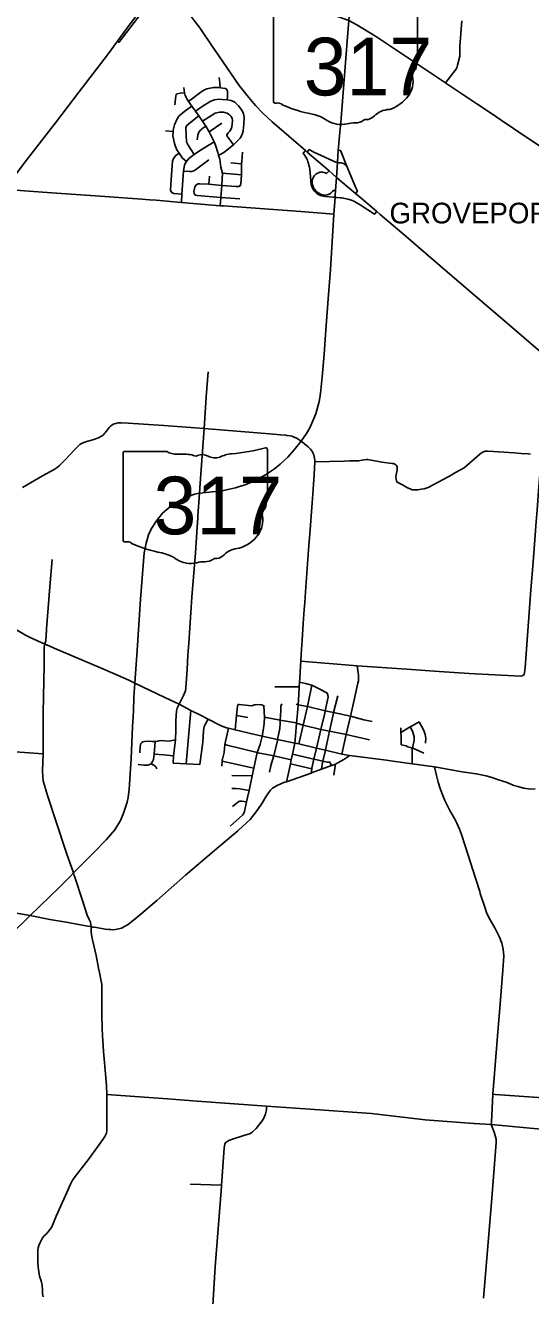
# Model space of a CAD drawing. Extents: x 1755200 to 1902939, y 644115 to 788070.
# Drawn here: x 1853497 to 1865704, y 661397 to 692073 of the extents above; entities that cross this region are included whole.
import ezdxf

# ---------------------------------------------------------------- set-up
doc = ezdxf.new("R2010")
doc.units = 0
for name, color, linetype in [('GM_X_City_Street', 7, 'Continuous'), ('GM_X_Corporation_Text', 7, 'Continuous'), ('GM_X_County_Road', 7, 'Continuous'), ('GM_X_Interchange_Ramps', 7, 'Continuous'), ('GM_X_Interstate_Route', 7, 'Continuous'), ('GM_X_State_Route', 7, 'Continuous'), ('GM_X_State_Shield', 7, 'Continuous'), ('GM_X_Township_Road', 7, 'Continuous'), ('GM_X_US_Route', 7, 'Continuous')]:
    doc.layers.add(name, color=color, linetype=linetype)

msp = doc.modelspace()

# ---------------------------------------------------------------- linework, layer by layer
at = {"layer": 'GM_X_City_Street'}
for points in [[(1860916, 692337), (1860948, 692324), (1861312, 692190), (1861508, 692091), (1861979, 691797), (1862752, 691283), (1863647, 690689), (1863658, 690682)], [(1858203, 687718), (1858220, 687916), (1858243, 688207), (1858260, 688504), (1858218, 688646), (1858192, 688840), (1858165, 688941), (1858149, 689003), (1858090, 689179), (1858055, 689260), (1857940, 689505), (1857859, 689641), (1857776, 689762), (1857687, 689888), (1857603, 690006), (1857519, 690120), (1857439, 690237), (1857411, 690278), (1857358, 690378), (1857340, 690447), (1857321, 690573)], [(1857439, 690237), (1857737, 690458), (1857805, 690506), (1857883, 690538), (1857959, 690561), (1858045, 690573), (1858206, 690570), (1858212, 690569), (1858334, 690548), (1858360, 690528), (1858380, 690484), (1858382, 690426), (1858379, 690345), (1858375, 690275)], [(1858206, 690570), (1858197, 690688), (1858181, 690816)], [(1857110, 690157), (1857129, 690373), (1857141, 690407), (1857167, 690422), (1857240, 690436), (1857340, 690447)], [(1857603, 690006), (1857796, 690131), (1857974, 690246), (1858062, 690272), (1858168, 690289), (1858251, 690281), (1858375, 690275), (1858471, 690261), (1858558, 690218), (1858600, 690182), (1858644, 690134), (1858701, 690060), (1858733, 690010)], [(1857388, 688788), (1857294, 688867), (1857212, 688986), (1857158, 689067), (1857124, 689149), (1857099, 689219), (1857057, 689408), (1857066, 689509), (1857068, 689541), (1857098, 689671), (1857158, 689802), (1857207, 689880), (1857269, 689941), (1857383, 690023), (1857519, 690120)], [(1857776, 689762), (1858083, 689955), (1858194, 689982), (1858280, 689980), (1858376, 689952), (1858430, 689912), (1858461, 689878)], [(1858165, 688941), (1858219, 688961), (1858289, 689001), (1858523, 689193), (1858577, 689237), (1858689, 689353), (1858733, 689442), (1858759, 689530), (1858778, 689685), (1858780, 689859), (1858765, 689937), (1858747, 689978), (1858733, 690010)], [(1857577, 688958), (1857428, 689185), (1857390, 689264), (1857371, 689600), (1857391, 689644), (1857451, 689708), (1857687, 689888)], [(1857651, 689308), (1857660, 689420), (1857688, 689493), (1857724, 689541), (1857782, 689589), (1857859, 689641)], [(1857940, 689505), (1858243, 689715)], [(1858461, 689878), (1858489, 689832), (1858503, 689772), (1858495, 689700), (1858482, 689622), (1858468, 689577), (1858436, 689523), (1858400, 689475), (1858362, 689433), (1858364, 689417), (1858380, 689383), (1858419, 689335), (1858523, 689193)], [(1856878, 689524), (1857066, 689509)], [(1857267, 687797), (1857279, 687994), (1857320, 688555), (1857333, 688661), (1857343, 688701), (1857358, 688737), (1857388, 688788), (1857411, 688820), (1857447, 688863), (1857577, 688958), (1857704, 689045), (1858055, 689260)], [(1858723, 688784), (1858723, 688787), (1858743, 689011)], [(1857279, 687994), (1857080, 688013), (1857033, 688035), (1856999, 688083), (1857010, 688238), (1857048, 688791), (1857074, 688856), (1857135, 688935), (1857212, 688986)], [(1857320, 688555), (1857473, 688545), (1857517, 688544), (1857553, 688555), (1857604, 688589), (1857927, 688829)], [(1858461, 688755), (1858718, 688732)], [(1858653, 688181), (1858685, 688198), (1858706, 688245), (1858721, 688463), (1858718, 688732), (1858723, 688784)], [(1857931, 688236), (1857948, 688434)], [(1858260, 688504), (1858721, 688463)], [(1853256, 688094), (1854025, 688040), (1855415, 687939), (1856313, 687875), (1856498, 687863), (1856659, 687849)], [(1857575, 688092), (1857568, 688060), (1857572, 688013), (1857600, 687977), (1857651, 687962), (1858220, 687916), (1858225, 687915)], [(1857575, 688092), (1857592, 688175), (1857626, 688224), (1857674, 688251), (1857713, 688251), (1857931, 688236), (1858243, 688207), (1858590, 688183), (1858653, 688181)], [(1856659, 687849), (1857267, 687797), (1858203, 687718), (1858280, 687713)], [(1858225, 687915), (1858677, 687884)], [(1858280, 687713), (1860155, 687580), (1860950, 687512)], [(1857862, 683100), (1857912, 683710)], [(1857819, 682336), (1857861, 683093), (1857862, 683100)], [(1853426, 680912), (1853522, 680967), (1853910, 681193), (1854189, 681352), (1854261, 681400), (1854318, 681445), (1854378, 681497), (1854453, 681572), (1854570, 681699), (1854684, 681827), (1854744, 681888), (1854816, 681949), (1854871, 681982), (1854933, 682010), (1855003, 682031), (1855128, 682068), (1855265, 682112), (1855307, 682133), (1855338, 682154), (1855372, 682181), (1855399, 682207), (1855422, 682234), (1855522, 682365), (1855552, 682391), (1855579, 682412), (1855608, 682431), (1855645, 682450), (1855680, 682462), (1855708, 682470), (1855738, 682474), (1855770, 682476), (1855812, 682476), (1855976, 682468), (1856838, 682407), (1857819, 682336), (1859494, 682198), (1859660, 682184), (1859789, 682175), (1859814, 682172)], [(1857662, 680176), (1857665, 680229), (1857704, 680773), (1857718, 681019), (1857819, 682336)], [(1859814, 682172), (1859893, 682164), (1859935, 682152), (1859974, 682139), (1860060, 682093), (1860156, 682029), (1860241, 681965), (1860329, 681899), (1860364, 681866), (1860388, 681838), (1860410, 681809), (1860430, 681778), (1860444, 681747), (1860464, 681703), (1860478, 681662), (1860486, 681621), (1860490, 681577), (1860492, 681535)], [(1863741, 681190), (1863892, 681274), (1864098, 681392), (1864474, 681719), (1864509, 681742), (1864533, 681756), (1864567, 681774), (1864606, 681792), (1864653, 681792)], [(1860247, 678135), (1860266, 678393), (1860341, 679406), (1860379, 679897), (1860436, 680648), (1860456, 680984), (1860475, 681227), (1860492, 681535)], [(1860492, 681535), (1861199, 681551), (1861335, 681555), (1861455, 681558), (1861492, 681557)], [(1861492, 681557), (1861502, 681557), (1861556, 681559), (1861629, 681570), (1861687, 681581), (1861735, 681586), (1861771, 681587), (1861800, 681585), (1861989, 681549), (1862111, 681528), (1862357, 681496), (1862384, 681490), (1862404, 681484), (1862427, 681476), (1862447, 681463), (1862461, 681447), (1862473, 681431), (1862476, 681417), (1862480, 681396), (1862480, 681371), (1862477, 681340), (1862456, 681216), (1862451, 681165), (1862455, 681118), (1862467, 681076), (1862477, 681042), (1862607, 680976), (1862731, 680909), (1862790, 680878), (1862844, 680860), (1862898, 680854), (1862977, 680858), (1863058, 680870), (1863132, 680885), (1863225, 680913), (1863231, 680916)], [(1852124, 678291), (1852293, 678171), (1852973, 677678), (1853115, 677579), (1853151, 677554), (1853239, 677497), (1853496, 677349), (1853612, 677287), (1853964, 677130), (1854004, 677115)], [(1853964, 677130), (1853984, 677186), (1853988, 677214), (1854008, 677475)], [(1853947, 676655), (1853951, 677068), (1853964, 677130)], [(1854004, 677115), (1854012, 677112), (1854194, 677034), (1854360, 676964), (1854629, 676848), (1855315, 676556), (1855608, 676432), (1855996, 676257), (1856143, 676188)], [(1857211, 675679), (1857307, 675873), (1857343, 675944), (1857362, 676003), (1857372, 676074), (1857405, 676517), (1857425, 676868), (1857431, 676963)], [(1856143, 676188), (1856869, 675838), (1857211, 675679), (1857493, 675528), (1857729, 675414), (1857909, 675320), (1858229, 675159), (1858353, 675112), (1858401, 675102), (1858567, 675061), (1858669, 675037)], [(1860005, 674735), (1860027, 674918), (1860049, 675225), (1860068, 675462), (1860084, 675668), (1860100, 675913), (1860114, 676102), (1860121, 676212), (1860127, 676304)], [(1860101, 674719), (1860206, 675175), (1860309, 675622), (1860415, 676136)], [(1860121, 676212), (1860267, 676183), (1860415, 676136), (1860610, 676040), (1860784, 675958), (1860801, 675911)], [(1859525, 676101), (1860114, 676102)], [(1860398, 674016), (1860415, 674121), (1860417, 674131), (1860468, 674353), (1860529, 674616), (1860637, 675067), (1860732, 675465), (1860743, 675520), (1860794, 675775), (1860809, 675847), (1860803, 675889), (1860801, 675911)], [(1860751, 674580), (1860847, 675025), (1860942, 675464), (1860945, 675477), (1861044, 675884)], [(1861141, 674476), (1861199, 674729), (1861246, 674946), (1861348, 675389), (1861464, 675893), (1861465, 675896)], [(1857069, 674256), (1857077, 674436), (1857126, 674822), (1857130, 675067), (1857131, 675278), (1857149, 675519), (1857161, 675580), (1857211, 675679)], [(1857380, 674241), (1857493, 675528)], [(1858567, 675061), (1858600, 675406), (1858619, 675635), (1858626, 675670)], [(1858626, 675670), (1858664, 675673), (1858886, 675651), (1858968, 675641), (1859031, 675665), (1859036, 675667), (1859045, 675668)], [(1859045, 675668), (1859101, 675674), (1859207, 675666), (1859237, 675652), (1859253, 675646)], [(1859173, 674715), (1859217, 674909), (1859242, 675045), (1859263, 675216), (1859277, 675363), (1859261, 675638), (1859263, 675628), (1859253, 675646)], [(1859585, 674801), (1859590, 674824), (1859641, 675093), (1859652, 675225), (1859654, 675295), (1859670, 675517), (1859672, 675634), (1859690, 675691)], [(1860042, 675679), (1860084, 675668), (1860309, 675622), (1860743, 675520), (1860945, 675477), (1861348, 675389), (1861674, 675303), (1861674, 675303)], [(1857714, 674224), (1857782, 674765), (1857798, 675037), (1857805, 675095), (1857817, 675140), (1857840, 675187), (1857909, 675320)], [(1858600, 675406), (1858871, 675360)], [(1859277, 675363), (1859654, 675295), (1860040, 675227)], [(1860040, 675227), (1860049, 675225), (1860206, 675175), (1860637, 675067), (1860847, 675025), (1861246, 674946), (1861813, 674817)], [(1861674, 675303), (1861872, 675258)], [(1862572, 674994), (1862793, 675132), (1862839, 675160), (1863013, 675254)], [(1863168, 674737), (1863170, 674857), (1863155, 674952), (1863122, 675042), (1863013, 675254)], [(1858257, 674353), (1858298, 674513), (1858319, 674709), (1858401, 675102)], [(1858669, 675037), (1858932, 674974), (1859217, 674909), (1859590, 674824), (1860005, 674735), (1860101, 674719), (1860529, 674616), (1860748, 674568), (1861141, 674476), (1861281, 674450)], [(1862577, 674702), (1862577, 674909), (1862572, 674994), (1862566, 675109)], [(1862840, 674240), (1862843, 674606), (1862847, 674619), (1862855, 674642), (1862869, 674698), (1862894, 674802), (1862893, 674888), (1862857, 675003), (1862824, 675074), (1862793, 675132)], [(1856259, 674506), (1856270, 674658), (1856276, 674702), (1856290, 674728), (1856310, 674754), (1856332, 674768), (1856376, 674782), (1856475, 674787), (1856557, 674781), (1856629, 674779)], [(1856539, 674242), (1856571, 674298), (1856589, 674342), (1856606, 674472), (1856629, 674779)], [(1856629, 674779), (1856693, 674791), (1856723, 674797), (1856765, 674800), (1856974, 674791), (1857003, 674797)], [(1857003, 674797), (1857126, 674822)], [(1858319, 674709), (1858368, 674687), (1858734, 674599)], [(1858447, 672732), (1858741, 673000), (1858767, 673034), (1858789, 673090), (1858841, 673322), (1858864, 673426), (1858902, 673599), (1858977, 673948), (1859018, 674134), (1859099, 674510), (1859170, 674704), (1859173, 674715)], [(1858734, 674599), (1859099, 674510), (1859124, 674505), (1859500, 674433), (1859919, 674339)], [(1859428, 674203), (1859500, 674433), (1859585, 674801)], [(1859806, 673807), (1859808, 673808), (1859845, 673982), (1859899, 674242), (1859919, 674339), (1859950, 674475), (1860005, 674735)], [(1860685, 674301), (1860687, 674307), (1860748, 674568), (1860748, 674568), (1860751, 674580)], [(1862577, 674702), (1862696, 674671), (1862741, 674653), (1862847, 674619), (1862855, 674616), (1862986, 674563), (1863126, 674500)], [(1854233, 672859), (1854030, 673476), (1853929, 673830), (1853917, 673924), (1853914, 674072), (1853927, 674485)], [(1856606, 674472), (1856841, 674454), (1856841, 674454)], [(1856841, 674454), (1857077, 674436)], [(1858246, 674186), (1858252, 674302), (1858254, 674341), (1858257, 674353)], [(1858252, 674302), (1859018, 674134)], [(1859950, 674475), (1860468, 674353), (1860477, 674351), (1860687, 674307), (1860790, 674281), (1860813, 674279), (1860843, 674286), (1860896, 674197)], [(1860410, 674021), (1860655, 674113), (1860896, 674197), (1860971, 674226), (1861189, 674344), (1861264, 674392), (1861324, 674441)], [(1860655, 674113), (1860678, 674271), (1860685, 674301)], [(1861281, 674450), (1861324, 674441), (1862222, 674325), (1862373, 674304)], [(1856220, 674223), (1856360, 674205), (1856452, 674206), (1856495, 674220), (1856539, 674242)], [(1856672, 674115), (1856653, 674159), (1856629, 674182), (1856599, 674208), (1856539, 674242)], [(1857069, 674256), (1857380, 674241), (1857714, 674224)], [(1859393, 674038), (1859426, 674195), (1859428, 674203)], [(1859808, 673808), (1860398, 674016), (1860410, 674021)], [(1859899, 674242), (1860415, 674121)], [(1860953, 673963), (1860982, 674183), (1860979, 674205), (1860971, 674226)], [(1858488, 673957), (1858977, 673948)], [(1859433, 673618), (1859447, 673630), (1859471, 673651), (1859562, 673712), (1859697, 673771), (1859765, 673793), (1859806, 673807)], [(1858481, 673646), (1858589, 673642), (1858679, 673633), (1858902, 673599)], [(1858497, 673209), (1858656, 673329), (1858680, 673335), (1858726, 673339), (1858841, 673322)], [(1854688, 671502), (1854675, 671541), (1854661, 671604), (1854486, 672082), (1854233, 672859)], [(1855134, 670298), (1855213, 670285), (1855425, 670250), (1855514, 670239), (1855561, 670236), (1855627, 670231), (1855715, 670247), (1855815, 670274), (1855892, 670309), (1855978, 670357), (1856284, 670609), (1856670, 670935), (1857365, 671549), (1858064, 672147), (1858630, 672623), (1858644, 672636)]]:
    msp.add_lwpolyline(points, dxfattribs=at)
at = {"layer": 'GM_X_County_Road'}
for points in [[(1863647, 690689), (1863896, 691006), (1863919, 691045), (1863941, 691117), (1863997, 691334), (1863994, 691569), (1864043, 692185)], [(1863658, 690682), (1864403, 690179), (1864782, 689927), (1864994, 689782), (1865287, 689585), (1865588, 689386), (1866376, 688859), (1866561, 688728), (1866664, 688651), (1866709, 688615)], [(1861513, 676603), (1862717, 676522), (1863496, 676469), (1864217, 676423), (1865458, 676355), (1865501, 676361), (1865531, 676379), (1865551, 676407), (1865559, 676440), (1865570, 676568), (1865711, 678443), (1865747, 678914), (1865778, 679328), (1865812, 679763), (1865837, 680091), (1865860, 680367), (1865898, 680836), (1865941, 681419), (1865951, 681544)], [(1857431, 676963), (1857442, 677153), (1857522, 678265), (1857604, 679332), (1857649, 679956), (1857662, 680176)], [(1860145, 676618), (1860153, 676717), (1860162, 676886), (1860184, 677224), (1860212, 677628), (1860234, 677965), (1860247, 678135)], [(1860127, 676304), (1860144, 676609), (1860145, 676618)], [(1861465, 675896), (1861529, 676184), (1861543, 676244), (1861549, 676293), (1861547, 676345), (1861543, 676392), (1861537, 676434), (1861513, 676603)], [(1862373, 674304), (1862840, 674240), (1863384, 674164), (1864053, 674044), (1864390, 674002), (1864630, 673951), (1864765, 673913), (1864929, 673857), (1865112, 673799), (1865280, 673728), (1865294, 673721), (1865297, 673720)], [(1864489, 671105), (1864473, 671154), (1864377, 671452), (1864120, 672259), (1864031, 672532), (1863985, 672663), (1863920, 672805), (1863863, 672918), (1863756, 673115), (1863634, 673354), (1863566, 673518), (1863515, 673643), (1863470, 673796), (1863426, 673955), (1863384, 674164)], [(1865297, 673720), (1865397, 673692), (1865536, 673653), (1865708, 673630), (1865811, 673635)], [(1858644, 672636), (1858928, 672897), (1859009, 672997), (1859110, 673134), (1859218, 673292), (1859309, 673446), (1859370, 673541), (1859420, 673607), (1859433, 673618)], [(1855082, 670307), (1855077, 670356), (1855067, 670412), (1855039, 670479), (1854992, 670586), (1854875, 670941), (1854688, 671502)], [(1864970, 668444), (1865034, 669256), (1865054, 669593), (1865039, 669765), (1865007, 669911), (1864949, 670055), (1864841, 670275), (1864704, 670513), (1864640, 670647), (1864594, 670775), (1864489, 671105)], [(1852096, 670831), (1853612, 670573)], [(1853612, 670573), (1854085, 670484), (1854528, 670409), (1854778, 670361)], [(1854778, 670361), (1854785, 670360), (1854999, 670321), (1855082, 670307)], [(1855343, 668206), (1855343, 668329), (1855342, 668614), (1855345, 668809), (1855341, 668910), (1855330, 668988), (1855286, 669200), (1855262, 669308), (1855207, 669612), (1855120, 669991), (1855095, 670107), (1855089, 670185), (1855082, 670307)], [(1855082, 670307), (1855134, 670298)], [(1864756, 665581), (1864756, 665582), (1864793, 666258), (1864900, 667663), (1864970, 668440), (1864970, 668444)], [(1855462, 666252), (1855453, 666460), (1855444, 666664), (1855384, 667293), (1855359, 667683), (1855351, 667833), (1855343, 668206)], [(1853907, 661550), (1853904, 661622), (1853899, 661649), (1853876, 661750), (1853840, 661863), (1853806, 662080), (1853797, 662207), (1853798, 662372), (1853800, 662491), (1853809, 662551), (1853824, 662606), (1853844, 662666), (1853874, 662727), (1853911, 662789), (1853958, 662845), (1853993, 662875), (1854045, 662935), (1854117, 663031), (1854141, 663077), (1854242, 663315), (1854353, 663562), (1854498, 663888), (1854588, 664085), (1854636, 664182), (1854702, 664271), (1855010, 664676), (1855248, 664999), (1855370, 665164), (1855418, 665236), (1855436, 665272), (1855455, 665316), (1855465, 665381), (1855465, 665667), (1855462, 666252)], [(1855462, 666252), (1856483, 666179), (1856930, 666146), (1857651, 666095), (1859326, 665971), (1860259, 665910), (1861859, 665794), (1863158, 665640), (1864334, 665557)], [(1864334, 665557), (1864338, 665557), (1864754, 665527)], [(1864569, 661334), (1864755, 663649), (1864875, 665092), (1864872, 665174), (1864827, 665345), (1864754, 665527), (1864756, 665581)], [(1864754, 665527), (1865692, 665442), (1866128, 665403), (1867408, 665311), (1867785, 665280), (1867804, 665280)], [(1853925, 661369), (1853910, 661437), (1853907, 661550)]]:
    msp.add_lwpolyline(points, dxfattribs=at)
at = {"layer": 'GM_X_Interchange_Ramps'}
for points in [[(1855721, 691691), (1855756, 691664), (1856207, 692249), (1856560, 692706), (1856777, 692989), (1857026, 693309), (1857514, 693941), (1857648, 694112), (1857735, 694222), (1858124, 694717), (1858076, 694754)], [(1860265, 689050), (1860207, 688985), (1860247, 688929), (1860271, 688891), (1860294, 688849), (1860310, 688815), (1860324, 688779), (1860338, 688738), (1860349, 688699), (1860360, 688646), (1860366, 688593), (1860404, 688229), (1860417, 688181), (1860432, 688145), (1860450, 688113), (1860475, 688077), (1860507, 688042), (1860533, 688020), (1860565, 687998), (1860598, 687980), (1860627, 687968), (1860665, 687957), (1860700, 687951), (1860747, 687943), (1860938, 687925), (1860978, 687922)], [(1861038, 688759), (1861010, 688760), (1860467, 689011), (1860355, 689074), (1860305, 689015)], [(1861471, 688017), (1861520, 688071), (1861478, 688150), (1861257, 688688), (1861132, 688992), (1861109, 689054), (1861058, 689057)], [(1861257, 688688), (1861245, 688683), (1861226, 688703), (1861204, 688721), (1861179, 688735), (1861150, 688747), (1861124, 688753), (1861105, 688755), (1861086, 688756), (1861038, 688759)], [(1860991, 688085), (1860937, 688089), (1860918, 688063), (1860893, 688037), (1860866, 688016), (1860838, 688000), (1860812, 687989), (1860786, 687981), (1860750, 687975), (1860715, 687974), (1860681, 687978), (1860644, 687988), (1860585, 688020), (1860545, 688048), (1860511, 688080), (1860480, 688120), (1860461, 688153), (1860448, 688184), (1860435, 688227), (1860428, 688271), (1860428, 688317), (1860437, 688366), (1860449, 688396), (1860463, 688423), (1860481, 688447), (1860511, 688477), (1860541, 688498), (1860577, 688515), (1860611, 688525), (1860645, 688529), (1860684, 688528), (1860715, 688522), (1860741, 688514), (1860776, 688498), (1860836, 688560)], [(1860978, 687922), (1861013, 687919), (1861112, 687912), (1861146, 687909), (1861184, 687903), (1861291, 687879), (1861374, 687852), (1861450, 687818), (1861516, 687784), (1861583, 687744), (1861930, 687513), (1861985, 687576)]]:
    msp.add_lwpolyline(points, dxfattribs=at)
at = {"layer": 'GM_X_Interstate_Route'}
for points in [[(1856737, 693020), (1856457, 692670), (1856025, 692109), (1855721, 691691)], [(1855721, 691691), (1855482, 691365), (1854785, 690465), (1854227, 689720), (1853491, 688775), (1852994, 688113)]]:
    msp.add_lwpolyline(points, dxfattribs=at)
at = {"layer": 'GM_X_State_Route'}
for points in [[(1861082, 689327), (1861118, 689728), (1861270, 691692), (1861312, 692190), (1861342, 692610)], [(1861072, 689219), (1861082, 689327)], [(1861015, 688403), (1861038, 688759), (1861058, 689057), (1861072, 689219)], [(1860982, 687976), (1860991, 688085), (1861015, 688403)], [(1860950, 687512), (1860978, 687922), (1860982, 687976)], [(1856430, 679624), (1856472, 679768), (1856544, 679921), (1856661, 680105), (1856809, 680290), (1857017, 680470), (1857125, 680541), (1857279, 680626), (1857475, 680711), (1857585, 680749), (1857704, 680773), (1858242, 680836), (1858431, 680872), (1858575, 680904), (1858844, 680992), (1859077, 681097), (1859302, 681221), (1859512, 681366), (1859654, 681474), (1859840, 681648), (1859988, 681821), (1860156, 682029), (1860291, 682215), (1860366, 682357), (1860443, 682525), (1860511, 682693), (1860595, 682989), (1860623, 683127), (1860637, 683268), (1860670, 683583), (1860712, 684123), (1860745, 684612), (1860816, 685471), (1860868, 686179), (1860950, 687512)], [(1856143, 676188), (1856195, 676985), (1856281, 678215), (1856367, 679337), (1856415, 679572), (1856430, 679624)], [(1856102, 675399), (1856109, 675507), (1856120, 675852), (1856143, 676188)], [(1854772, 671716), (1855159, 672106), (1855452, 672408), (1855656, 672644), (1855793, 672869), (1855865, 673048), (1855955, 673310), (1855982, 673423), (1856008, 673625), (1856056, 674364), (1856086, 675140), (1856101, 675376), (1856102, 675399)], [(1848819, 666696), (1849099, 666688), (1849232, 666701), (1849354, 666722), (1849455, 666750), (1849554, 666780), (1849673, 666832), (1849786, 666895), (1850303, 667340), (1851168, 668195), (1852000, 669022), (1852811, 669805), (1853162, 670133), (1853612, 670573), (1854310, 671256), (1854583, 671527)], [(1854583, 671527), (1854661, 671604), (1854772, 671716)]]:
    msp.add_lwpolyline(points, dxfattribs=at)
at = {"layer": 'GM_X_State_Shield'}
for p, q in [((1862974, 691331), (1862974, 692436)), ((1859493, 692347), (1859493, 690234)), ((1862973, 691331), (1862974, 691331)), ((1855863, 681748), (1855863, 679634)), ((1856916, 681784), (1855897, 681784)), ((1859343, 680731), (1859343, 681836)), ((1859343, 680731), (1859343, 680731))]:
    msp.add_line(p, q, dxfattribs=at)
for centre, major_axis, start_param, end_param in [((1862965, 691250), (60, 0), 1.883978, 3.671073), ((1862583, 691110), (360, 0), 5.934695, 6.695948), ((1862932, 691326), (41.5, 0), 5.05454, 6.418171), ((1861941, 690727), (923, 0), 5.101752, 6.440018), ((1863113, 690868), (262, 0), 2.387724, 3.262537), ((1859534, 690230), (40.7, 0), 3.00124, 4.508301), ((1859540, 690446), (310, 0), 4.665946, 4.897461), ((1859603, 690112), (112, 0), 0.519207, 1.627899), ((1861017, 692011), (2665, 0), 4.195997, 4.488961), ((1860222, 689285), (834, 0), 0.823519, 1.323587), ((1862330, 689641), (506, 0), 1.647645, 2.488434), ((1861124, 690102), (529, 0), 4.026481, 4.996735), ((1861430, 689371), (435, 0), 1.495662, 1.94098), ((1861468, 689943), (282, 0), 4.691044, 5.507374), ((1861723, 689739), (79.4, 0), 1.147584, 2.315152), ((1861689, 690029), (298, 0), 4.937069, 5.64225), ((1855902, 681752), (40.3, 0), 1.712693, 3.28349), ((1857159, 682029), (391, 0), 4.042523, 4.731795), ((1857289, 680597), (1404, 0), 1.404758, 1.657858), ((1857607, 681763), (113, 0), 3.836095, 5.185415), ((1857773, 681519), (235, 0), 0.950623, 2.079405), ((1858076, 681854), (282, 0), 4.081561, 5.145723), ((1858574, 681138), (743, 0), 1.699011, 2.107814), ((1858103, 684665), (3691, 0), 4.814394, 5.042369), ((1859304, 681841), (38.7, 0), 6.141152, 7.989035), ((1859302, 680727), (41.5, 0), 5.05454, 6.418171), ((1859482, 680268), (262, 0), 2.387724, 3.262537), ((1859334, 680650), (60, 0), 1.883978, 3.671073), ((1858953, 680510), (360, 0), 5.934695, 6.695948), ((1858310, 680128), (923, 0), 5.101752, 6.440018), ((1855903, 679630), (40.7, 0), 3.00124, 4.508301), ((1855909, 679846), (310, 0), 4.665946, 4.897461), ((1855973, 679512), (112, 0), 0.519207, 1.627899), ((1857386, 681411), (2665, 0), 4.195997, 4.488961), ((1856591, 678685), (834, 0), 0.823519, 1.323587), ((1857837, 679344), (282, 0), 4.691044, 5.507374), ((1858093, 679139), (79.4, 0), 1.147584, 2.315152), ((1858059, 679429), (298, 0), 4.937069, 5.64225), ((1858699, 679041), (506, 0), 1.647645, 2.488434), ((1857493, 679502), (529, 0), 4.026481, 4.996735), ((1857799, 678771), (435, 0), 1.495662, 1.94098)]:
    msp.add_ellipse(centre, major_axis=major_axis, ratio=0.8, start_param=start_param, end_param=end_param, dxfattribs=at)
at = {"layer": 'GM_X_Township_Road'}
for points in [[(1864653, 681792), (1864678, 681792), (1865310, 681749), (1865473, 681738), (1865653, 681725), (1865704, 681722)], [(1863231, 680916), (1863712, 681174), (1863741, 681190)], [(1854008, 677475), (1854010, 677499), (1854088, 678515), (1854140, 679172)], [(1853927, 674485), (1853928, 675474), (1853947, 676619), (1853947, 676655)], [(1860153, 676717), (1861513, 676603)], [(1851819, 674632), (1851844, 674630), (1853364, 674525), (1853927, 674485)], [(1864793, 666258), (1864845, 666255)], [(1864845, 666255), (1867282, 666082), (1867340, 666075), (1867372, 666075), (1867416, 666052), (1867449, 666025), (1867457, 666003), (1867434, 665667), (1867408, 665311)], [(1858015, 661025), (1858084, 662089), (1858235, 664034), (1858237, 664062), (1858303, 664955), (1858319, 665061), (1858333, 665087), (1858364, 665113), (1858415, 665141), (1858502, 665176), (1858778, 665267), (1858933, 665312), (1858984, 665351), (1859074, 665434), (1859216, 665618), (1859264, 665696), (1859296, 665783), (1859319, 665883), (1859326, 665971)], [(1857478, 664093), (1857486, 664092), (1858237, 664062)]]:
    msp.add_lwpolyline(points, dxfattribs=at)
at = {"layer": 'GM_X_US_Route'}
for points in [[(1856652, 693074), (1856737, 693020), (1856777, 692989), (1856897, 692893), (1857063, 692753), (1857202, 692621), (1857327, 692490), (1857455, 692349), (1857598, 692163), (1857712, 692012), (1858010, 691573), (1858344, 691078), (1858661, 690619), (1858855, 690377), (1859060, 690138), (1859236, 689954), (1859458, 689742), (1860265, 689050), (1860305, 689015), (1860836, 688560), (1861015, 688403)], [(1861015, 688403), (1861471, 688017), (1861608, 687899)], [(1861608, 687899), (1861985, 687576), (1862065, 687507)], [(1862065, 687507), (1862694, 686973), (1863169, 686564), (1863517, 686267)], [(1863517, 686267), (1864034, 685824), (1865077, 684934), (1865996, 684144), (1866100, 684050), (1866211, 683955), (1866765, 683491), (1867122, 683185), (1867715, 682659), (1867973, 682400), (1868205, 682168), (1868727, 681617), (1869171, 681145), (1869529, 680799), (1869787, 680588), (1869991, 680435), (1870216, 680279), (1870485, 680114), (1872095, 679234), (1873802, 678296), (1873853, 678268)]]:
    msp.add_lwpolyline(points, dxfattribs=at)

# ---------------------------------------------------------------- texts
at = {"layer": 'GM_X_Corporation_Text'}
msp.add_text('GROVEPORT', height=500, rotation=0, dxfattribs=at).set_placement((1862294, 687291))
at = {"layer": 'GM_X_State_Shield'}
for p in [(1860223, 690383), (1856592, 679783)]:
    msp.add_text('317', height=1392.2, dxfattribs=at).set_placement(p)

doc.saveas('drawing.dxf')
